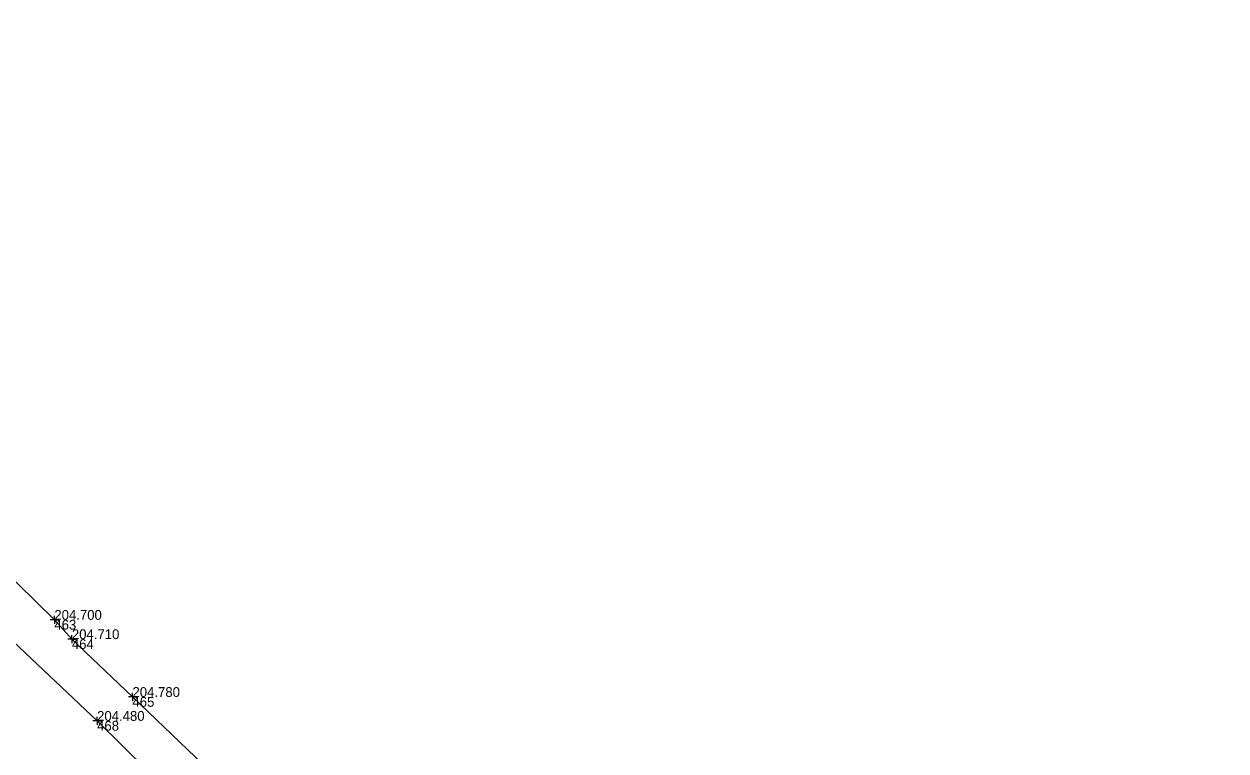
# Model space of a CAD drawing. Extents: x -744883 to -744469, y -966832 to -966374.
# Drawn here: x -744557.8 to -744484.5, y -966750.1 to -966705.7 of the extents above; entities that cross this region are included whole.
import ezdxf

# ---------------------------------------------------------------- set-up
doc = ezdxf.new("R2010")
doc.units = 0
for name, color, linetype in [('Body polohopisu', 7, 'Continuous'), ('Ploty_opěrné zdi', 7, 'Continuous'), ('Rozhraní ploch', 7, 'Continuous'), ('Vstup na pozemek', 7, 'Continuous'), ('Výšky bodů', 7, 'Continuous'), ('Čísla bodů', 7, 'Continuous')]:
    doc.layers.add(name, color=color, linetype=linetype)

msp = doc.modelspace()

# ---------------------------------------------------------------- linework, layer by layer
at = {"layer": 'Body polohopisu'}
for p, q in [((-744555.99, -966742.05), (-744556.24, -966742.05)), ((-744555.99, -966742.05), (-744555.99, -966741.8)), ((-744555.99, -966742.05), (-744555.74, -966742.05)), ((-744555.99, -966742.05), (-744555.99, -966742.3)), ((-744554.92, -966743.23), (-744555.17, -966743.23)), ((-744554.92, -966743.23), (-744554.92, -966742.98)), ((-744554.92, -966743.23), (-744554.67, -966743.23)), ((-744554.92, -966743.23), (-744554.92, -966743.48)), ((-744551.22, -966746.76), (-744551.47, -966746.76)), ((-744551.22, -966746.76), (-744551.22, -966746.51)), ((-744551.22, -966746.76), (-744550.97, -966746.76)), ((-744551.22, -966746.76), (-744551.22, -966747.01)), ((-744553.38, -966748.22), (-744553.63, -966748.22)), ((-744553.38, -966748.22), (-744553.38, -966747.97)), ((-744553.38, -966748.22), (-744553.13, -966748.22)), ((-744553.38, -966748.22), (-744553.38, -966748.47))]:
    msp.add_line(p, q, dxfattribs=at)
at = {"layer": 'Ploty_opěrné zdi'}
for points in [[(-744571.69, -966726.63), (-744555.99, -966742.05)], [(-744555.99, -966742.05), (-744554.92, -966743.23)], [(-744551.22, -966746.76), (-744538.72, -966758.72)]]:
    msp.add_lwpolyline(points, dxfattribs=at)
at = {"layer": 'Rozhraní ploch'}
msp.add_lwpolyline([(-744484.45, -966802.29), (-744488.93, -966807.11), (-744494.18, -966806.31), (-744504.16, -966796.59), (-744523.84, -966777.07), (-744535.89, -966765.33), (-744540.85, -966760.58), (-744553.38, -966748.22), (-744567.31, -966735.07), (-744575.15, -966727.6), (-744592.64, -966710.64), (-744593.17, -966705.66)], dxfattribs=at)
at = {"layer": 'Vstup na pozemek'}
msp.add_lwpolyline([(-744554.92, -966743.23), (-744551.22, -966746.76)], dxfattribs=at)

# ---------------------------------------------------------------- texts
at = {"layer": 'Výšky bodů'}
for s, p in [('204.700', (-744555.99, -966742.05)), ('204.710', (-744554.92, -966743.23)), ('204.780', (-744551.22, -966746.76)), ('204.480', (-744553.38, -966748.22))]:
    msp.add_text(s, height=0.6, dxfattribs=at).set_placement(p)
at = {"layer": 'Čísla bodů'}
for s, p in [('463', (-744555.99, -966742.65)), ('464', (-744554.92, -966743.83)), ('465', (-744551.22, -966747.36)), ('468', (-744553.38, -966748.82))]:
    msp.add_text(s, height=0.6, dxfattribs=at).set_placement(p)

doc.saveas('drawing.dxf')
